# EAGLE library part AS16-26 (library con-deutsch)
DEUTSCH Connector
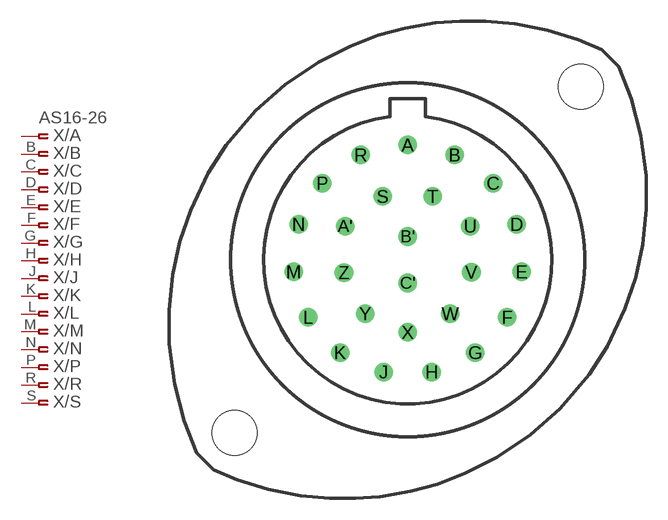
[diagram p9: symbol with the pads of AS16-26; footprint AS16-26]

Designator prefix X; gates /A=PINF_VAL /B=ASPINF /C=ASPINF /D=ASPINF /E=ASPINF /F=ASPINF /G=ASPINF /H=ASPINF /J=ASPINF /K=ASPINF /L=ASPINF /M=ASPINF /N=ASPINF /P=ASPINF /R=ASPINF /S=ASPINF /T=ASPINF /U=ASPINF /V=ASPINF /W=ASPINF /X=ASPINF /Y=ASPINF /Z=ASPINF /B'=ASPINF /C'=ASPINF /A'=ASPINF

## AS16-26 (OC_FARNELL: unknown; OC_NEWARK: unknown)  [AS16-26]
A  /A:1  pas
A'  /A':1  pas
B  /B:1  pas
B'  /B':1  pas
C  /C:1  pas
C'  /C':1  pas
D  /D:1  pas
E  /E:1  pas
F  /F:1  pas
G  /G:1  pas
H  /H:1  pas
J  /J:1  pas
K  /K:1  pas
L  /L:1  pas
M  /M:1  pas
N  /N:1  pas
P  /P:1  pas
R  /R:1  pas
S  /S:1  pas
T  /T:1  pas
U  /U:1  pas
V  /V:1  pas
W  /W:1  pas
X  /X:1  pas
Y  /Y:1  pas
Z  /Z:1  pas

## Footprint AS16-26 (pad centres in mm)
DEUTSCH Connector
drill 0.813 round: A 0,8.153; A' -4.445,2.388; B 3.327,7.442; B' 0,1.651; C 6.071,5.436; C' 0,-1.651; D 7.747,2.515; E 8.103,-0.864; F 7.061,-4.089; G 4.801,-6.604; H 1.702,-7.976; J -1.702,-7.976; K -4.801,-6.604; L -7.061,-4.089; M -8.103,-0.864; N -7.747,2.515; P -6.071,5.436; R -3.327,7.442; S -1.778,4.496; T 1.778,4.496; U 4.445,2.388; V 4.521,-0.889; W 3.023,-3.835; X 0,-5.156; Y -3.023,-3.835; Z -4.521,-0.914
hole 3.2 at 12.29,12.29
hole 3.2 at -12.29,-12.29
